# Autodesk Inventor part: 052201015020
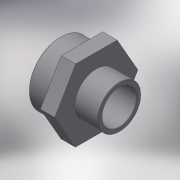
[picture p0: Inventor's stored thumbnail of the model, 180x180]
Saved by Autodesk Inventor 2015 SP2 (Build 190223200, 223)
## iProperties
Created: 2017-10
Part Number: 052201015020
Material: Generic
Description: PLASSON SOCKET NIPPLE THR. P 1.1/2"-2"
Document SubType Name: Modeling
Designer: KIM
Density: 1 g/cm^3
Appearance: Default
Author: KIM
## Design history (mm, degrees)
derived "052201.ipt"
feature "Solid1::052201.ipt"
tag "TaggingFeature1"
body "Solid1"
other parameters: "d0" = 66, "d13" = 0, "d14" = 0.56656, "d17" = 24, "d18" = 31.2, "d19" = 69.97016, "d20" = 56.656, "d21" = 47.803, "d22" = 19.2, "d23" = 53.8232, "d24" = 38.2424, "d25" = 26, "d26" = -24, "G_" = 56.656, "R_" = 47.803, "lt_1" = 24, "lt_" = 26, "H_" = 66
